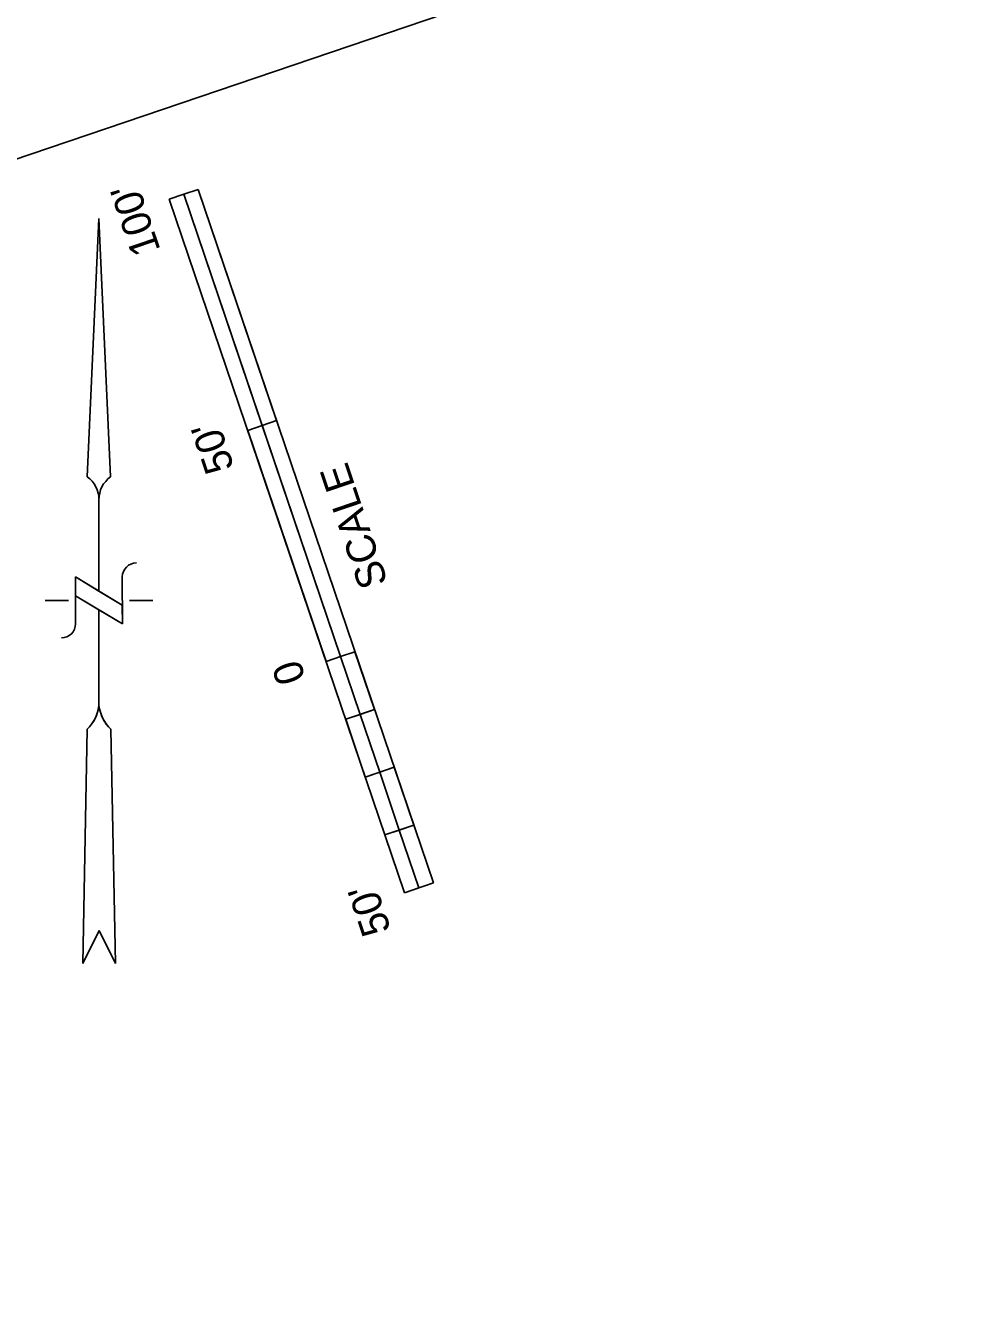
# Model space of a CAD drawing. Extents: x 2150575 to 2152290, y 141864 to 143954.
# Drawn here: x 2150781.7 to 2150972.9, y 143357 to 143617 of the extents above; entities that cross this region are included whole.
import ezdxf

# ---------------------------------------------------------------- set-up
doc = ezdxf.new("R2010")
doc.units = 0
for name, color, linetype in [('7', 7, 'Continuous'), ('Pr_Abut_ph4', 7, 'Continuous'), ('PR_Road_Concrete', 7, 'Continuous')]:
    doc.layers.add(name, color=color, linetype=linetype)

msp = doc.modelspace()

# ---------------------------------------------------------------- linework, layer by layer
at = {"layer": '7'}
for p, q in [((2150794.37, 143524.5), (2150796.76, 143577.39)), ((2150796.76, 143577.39), (2150794.37, 143524.5)), ((2150796.76, 143577.39), (2150799.18, 143524.5)), ((2150799.18, 143524.5), (2150796.76, 143577.39)), ((2150796.79, 143501.11), (2150796.78, 143519.82)), ((2150801.58, 143498.23), (2150791.99, 143503.99)), ((2150791.99, 143503.99), (2150801.58, 143498.23)), ((2150791.99, 143503.99), (2150791.99, 143494.39)), ((2150796.79, 143501.11), (2150791.99, 143503.99)), ((2150791.99, 143503.99), (2150791.99, 143500.15)), ((2150801.58, 143503.99), (2150801.59, 143494.4)), ((2150790.55, 143499.19), (2150785.75, 143499.19)), ((2150801.59, 143494.4), (2150791.99, 143500.15)), ((2150801.58, 143498.23), (2150796.79, 143501.11)), ((2150807.82, 143499.2), (2150803.02, 143499.19)), ((2150796.8, 143477.6), (2150796.79, 143497.27)), ((2150801.59, 143494.4), (2150801.58, 143498.23)), ((2150793.46, 143424.83), (2150794.4, 143472.8)), ((2150794.4, 143472.8), (2150793.46, 143424.83)), ((2150800.18, 143424.83), (2150799.2, 143472.81)), ((2150800.18, 143424.83), (2150799.2, 143472.81)), ((2150793.46, 143424.83), (2150796.81, 143431.55)), ((2150793.46, 143424.83), (2150796.81, 143431.55)), ((2150796.81, 143431.55), (2150800.18, 143424.83)), ((2150796.81, 143431.55), (2150800.18, 143424.83))]:
    msp.add_line(p, q, dxfattribs=at)
for points in [[(2150791.99, 143500.15), (2150796.79, 143497.27), (2150801.59, 143494.4)], [(2150796.8, 143477.6), (2150796.8, 143477.6), (2150796.79, 143477.6)]]:
    msp.add_lwpolyline(points, dxfattribs=at)
for centre, radius, start, end in [((2150791.02, 143519.82), 5.76, 0.0232, 54.4034), ((2150791.02, 143519.82), 5.76, 0.0232, 54.4034), ((2150802.54, 143519.82), 5.76, 125.6431, 180.0232), ((2150802.54, 143519.82), 5.76, 125.6431, 180.0232), ((2150804.46, 143503.99), 2.88, 90.0232, 180.0232), ((2150789.11, 143494.39), 2.88, 270.0232, 0.0232), ((2150788.44, 143478.76), 8.43, 314.9799, 352.4421), ((2150788.44, 143478.76), 8.43, 314.9799, 352.0822), ((2150805.15, 143478.77), 8.43, 187.6043, 225.0665), ((2150805.15, 143478.77), 8.43, 187.9642, 225.0665)]:
    msp.add_arc(centre, radius, start, end, dxfattribs=at)
at = {"layer": 'Pr_Abut_ph4'}
for p, q in [((2150811.2, 143581.37), (2150814.16, 143582.37)), ((2150814.16, 143582.37), (2150817.12, 143583.37)), ((2150817.12, 143583.37), (2150814.16, 143582.37)), ((2150846.29, 143487.67), (2150814.16, 143582.37)), ((2150814.16, 143582.37), (2150830.23, 143535.02)), ((2150865.31, 143441.33), (2150817.12, 143583.37)), ((2150833.19, 143536.02), (2150817.12, 143583.37)), ((2150859.39, 143439.32), (2150811.2, 143581.37)), ((2150833.19, 143536.02), (2150830.23, 143535.02)), ((2150830.23, 143535.02), (2150833.19, 143536.02)), ((2150830.23, 143535.02), (2150827.27, 143534.02)), ((2150830.23, 143535.02), (2150827.27, 143534.02)), ((2150827.27, 143534.02), (2150843.33, 143486.67)), ((2150846.29, 143487.67), (2150830.23, 143535.02)), ((2150849.25, 143488.68), (2150846.29, 143487.67)), ((2150849.25, 143488.68), (2150846.29, 143487.67)), ((2150853.26, 143476.84), (2150849.25, 143488.68)), ((2150846.29, 143487.67), (2150843.33, 143486.67)), ((2150843.33, 143486.67), (2150846.29, 143487.67)), ((2150850.3, 143475.83), (2150846.29, 143487.67)), ((2150846.29, 143487.67), (2150850.3, 143475.83)), ((2150847.35, 143474.83), (2150853.26, 143476.84)), ((2150850.3, 143475.83), (2150847.35, 143474.83)), ((2150850.3, 143475.83), (2150853.26, 143476.84)), ((2150854.32, 143464), (2150850.3, 143475.83)), ((2150854.32, 143464), (2150850.3, 143475.83)), ((2150847.35, 143474.83), (2150851.36, 143462.99)), ((2150851.36, 143462.99), (2150857.28, 143465)), ((2150851.36, 143462.99), (2150857.28, 143465)), ((2150851.36, 143462.99), (2150854.32, 143464)), ((2150857.28, 143465), (2150854.32, 143464)), ((2150858.34, 143452.16), (2150854.32, 143464)), ((2150854.32, 143464), (2150858.34, 143452.16)), ((2150861.3, 143453.16), (2150857.28, 143465)), ((2150855.38, 143451.16), (2150861.3, 143453.16)), ((2150858.34, 143452.16), (2150861.3, 143453.16)), ((2150858.34, 143452.16), (2150855.38, 143451.16)), ((2150855.38, 143451.16), (2150859.39, 143439.32)), ((2150862.35, 143440.32), (2150858.34, 143452.16)), ((2150862.35, 143440.32), (2150858.34, 143452.16)), ((2150859.39, 143439.32), (2150865.31, 143441.33)), ((2150859.39, 143439.32), (2150862.35, 143440.32))]:
    msp.add_line(p, q, dxfattribs=at)
at = {"layer": 'PR_Road_Concrete'}
msp.add_lwpolyline([(2151646.68, 143883.65), (2152152.67, 142392.14), (2151158.33, 142054.82), (2150652.34, 143546.33)], close=True, dxfattribs=at)

# ---------------------------------------------------------------- texts
at = {"layer": 'Pr_Abut_ph4'}
for s, p in [("100'", (2150809.46, 143570.95)), ("50'", (2150824.57, 143526.39)), ('SCALE', (2150856.06, 143502.85)), ('0', (2150839.23, 143483.19)), ("50'", (2150856.7, 143431.69))]:
    msp.add_text(s, height=6, rotation=108.7393, dxfattribs=at).set_placement(p)

doc.saveas('drawing.dxf')
